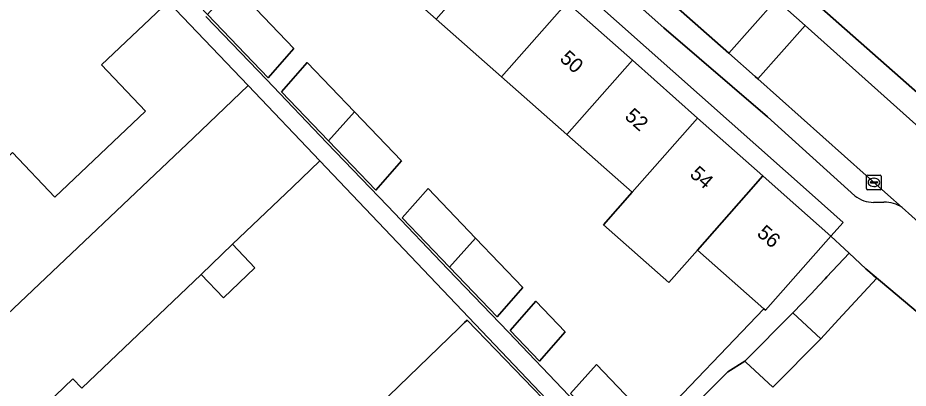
# Model space of a CAD drawing. Extents: x 162523 to 163266, y 381230 to 382050.
# Drawn here: x 162936.1 to 162997.1, y 381486.8 to 381512.1 of the extents above; entities that cross this region are included whole.
import ezdxf

# ---------------------------------------------------------------- set-up
doc = ezdxf.new("R2010")
doc.units = 0
for name, color, linetype in [('IMGEO_Erf', 7, 'Continuous'), ('IMGEO_Kolk', 7, 'Continuous'), ('IMGEO_Muur', 7, 'Continuous'), ('IMGEO_Pand', 7, 'Continuous'), ('IMGEO_Pand_nummerreeks', 7, 'Continuous'), ('IMGEO_Parkeervlak_open', 7, 'Continuous'), ('IMGEO_Rijbaan_lokaal_open', 7, 'Continuous'), ('IMGEO_Voetpad_open', 7, 'Continuous')]:
    doc.layers.add(name, color=color, linetype=linetype)

msp = doc.modelspace()

# ---------------------------------------------------------------- linework, layer by layer
at = {"layer": 'IMGEO_Erf'}
for points in [[(162979.592, 381528.722), (162975.111, 381532.694), (162970.631, 381536.665), (162966.151, 381540.636), (162961.584, 381544.684), (162956.963, 381548.78), (162952.356, 381552.864), (162947.718, 381556.975), (162944.876, 381553.79), (162964.471, 381536.308), (162999.264, 381505.633), (162999.351, 381505.556), (163000, 381506.279), (163002.177, 381508.703), (163000, 381510.633), (162997.512, 381512.838), (162993.032, 381516.809), (162988.552, 381520.78), (162984.072, 381524.751)], [(162952.337, 381533.894), (162951.47, 381532.913), (162955.868, 381529.014), (162960.335, 381525.054), (162964.802, 381521.094), (162969.269, 381517.134), (162973.736, 381513.174), (162978.203, 381509.214), (162982.67, 381505.254), (162987.138, 381501.293), (162988.597, 381500), (162991.799, 381497.161), (162992.639, 381498.114), (162990.515, 381500)], [(162953.249, 381508.02), (162949.104, 381512.345), (162945.876, 381515.714), (162947.643, 381517.713), (162950.871, 381514.344), (162955.016, 381510.02)], [(162959.161, 381505.694), (162962.39, 381502.325), (162960.624, 381500.325), (162957.395, 381503.695), (162954.167, 381507.063), (162955.933, 381509.063)], [(162967.45, 381497.045), (162970.697, 381493.657), (162968.931, 381491.657), (162965.683, 381495.045), (162962.438, 381498.432), (162964.205, 381500.432)], [(162971.597, 381492.718), (162973.605, 381490.623), (162971.838, 381488.624), (162969.831, 381490.718)], [(162966.696, 381491.253), (162966.876, 381491.427), (162976.591, 381481.38), (162976.41, 381481.206), (162969.171, 381474.207), (162968.934, 381474.452), (162959.589, 381484.117), (162959.457, 381484.253), (162966.311, 381490.881)]]:
    msp.add_lwpolyline(points, close=True, dxfattribs=at)
for points in [[(162948.991, 381512.217), (162953.136, 381507.892), (162957.281, 381503.566), (162961.425, 381499.243), (162965.57, 381494.917), (162969.718, 381490.59), (162973.859, 381486.269), (162977.616, 381482.348), (162977.739, 381482.466), (162973.972, 381486.397), (162975.739, 381488.396), (162979.659, 381484.306), (162987.204, 381492.203), (162982.656, 381496.222), (162980.699, 381494.008), (162976.227, 381497.959), (162978.183, 381500.174), (162973.709, 381504.128), (162969.235, 381508.081), (162964.762, 381512.033), (162960.288, 381515.986)], [(162935.735, 381502.902), (162938.652, 381499.847), (162944.855, 381505.737), (162941.842, 381508.894), (162946.401, 381513.222)], [(162903.859, 381500), (162947.952, 381453.669), (162957.442, 381462.564), (162967.253, 381472.252), (162976.751, 381481.351), (162956.799, 381502.326), (162954.918, 381500.53), (162950.818, 381496.616), (162952.35, 381495.012), (162950.188, 381492.947), (162948.656, 381494.551), (162940.499, 381486.762), (162939.885, 381487.405), (162933.973, 381481.762)], [(163001.938, 381488.428), (162994.2, 381494.937), (162994.918, 381494.271), (162992.317, 381491.468), (162991.116, 381490.145), (162987.816, 381486.838), (162985.97, 381488.548), (162985.898, 381488.614), (162984.752, 381487.882), (162980.521, 381483.642)]]:
    msp.add_lwpolyline(points, dxfattribs=at)
at = {"layer": 'IMGEO_Kolk'}
for p, q in [((162994.249, 381500.427), (162994.249, 381501.279)), ((162994.324, 381501.353), (162995.176, 381501.353)), ((162995.25, 381501.279), (162995.25, 381500.427)), ((162994.508, 381500.847), (162994.508, 381500.859)), ((162994.946, 381500.81), (162994.548, 381500.81)), ((162994.551, 381500.896), (162994.949, 381500.896)), ((162994.76, 381500.573), (162994.735, 381500.573)), ((162994.737, 381501.133), (162994.762, 381501.133)), ((162994.992, 381500.859), (162994.992, 381500.847)), ((162995.176, 381500.353), (162994.324, 381500.353))]:
    msp.add_line(p, q, dxfattribs=at)
for points in [[(162994.249, 381500.427), (162994.249, 381501.279)], [(162994.324, 381501.353), (162995.176, 381501.353)], [(162995.25, 381501.279), (162995.25, 381500.427)], [(162995.176, 381500.353), (162994.324, 381500.353)]]:
    msp.add_lwpolyline(points, dxfattribs=at)
for centre, radius, start, end in [((162994.326, 381501.277), 0.0765, 91.55205, 178.44795), ((162994.326, 381501.277), 0.0765, 91.55205, 178.44795), ((162995.174, 381501.277), 0.0765, 1.55205, 88.44795), ((162995.174, 381501.277), 0.0765, 1.55205, 88.44795), ((162994.548, 381500.856), 0.0403, 85.87752, 175.75265), ((162994.545, 381500.846), 0.0366, 178.93798, 274.71019), ((162994.949, 381500.853), 0.043, 264.86636, 352.45326), ((162994.953, 381500.858), 0.0386, 1.73085, 96.63898), ((162994.326, 381500.429), 0.0765, 181.55205, 268.44795), ((162994.326, 381500.429), 0.0765, 181.55205, 268.44795), ((162995.174, 381500.429), 0.0765, 271.55205, 358.44795), ((162995.174, 381500.429), 0.0765, 271.55205, 358.44795)]:
    msp.add_arc(centre, radius, start, end, dxfattribs=at)
for centre, major_axis, ratio, start_param, end_param in [((162994.736, 381500.853), (-0.387, 0.002), 0.722429, 4.712389, 7.853982), ((162994.761, 381500.853), (-0.39, 0.002), 0.717154, 1.570796, 4.712389)]:
    msp.add_ellipse(centre, major_axis=major_axis, ratio=ratio, start_param=start_param, end_param=end_param, dxfattribs=at)
at = {"layer": 'IMGEO_Muur'}
msp.add_lwpolyline([(162994.2, 381494.937), (163001.938, 381488.428)], dxfattribs=at)
at = {"layer": 'IMGEO_Pand'}
for points in [[(162960.288, 381515.986), (162964.762, 381512.033), (162969.269, 381517.134), (162964.802, 381521.094), (162964.729, 381521.012)], [(162969.235, 381508.081), (162973.736, 381513.174), (162969.269, 381517.134), (162964.762, 381512.033)], [(162950.871, 381514.344), (162949.104, 381512.345), (162953.249, 381508.02), (162955.016, 381510.02)], [(162933.844, 381493.401), (162935.349, 381491.825), (162935.374, 381491.799), (162948.134, 381503.914), (162951.885, 381507.475), (162946.401, 381513.222), (162941.842, 381508.894), (162944.855, 381505.737), (162938.652, 381499.847), (162935.735, 381502.902), (162930.729, 381498.15), (162932.581, 381496.211), (162931.838, 381495.502), (162928.973, 381492.767), (162927.06, 381494.771), (162926.828, 381494.547), (162920.503, 381488.564), (162921.104, 381487.935), (162921.086, 381487.132), (162921.802, 381486.381), (162922.707, 381486.36), (162924.5, 381484.482), (162928.117, 381487.935)], [(162978.203, 381509.214), (162973.736, 381513.174), (162969.235, 381508.081), (162973.709, 381504.128)], [(162978.203, 381509.214), (162973.709, 381504.128), (162978.183, 381500.174), (162982.67, 381505.254)], [(162955.933, 381509.063), (162954.167, 381507.063), (162957.395, 381503.695), (162959.161, 381505.694)], [(162954.918, 381500.53), (162956.799, 381502.326), (162951.885, 381507.475), (162948.134, 381503.914), (162935.374, 381491.799), (162925.959, 381482.861), (162926.338, 381482.463), (162929.997, 381478.63), (162930.329, 381478.283), (162933.973, 381481.762), (162939.885, 381487.405), (162940.499, 381486.762), (162948.656, 381494.551), (162950.818, 381496.616)], [(162959.161, 381505.694), (162957.395, 381503.695), (162960.624, 381500.325), (162962.39, 381502.325)], [(162987.138, 381501.293), (162982.67, 381505.254), (162978.183, 381500.174), (162976.227, 381497.959), (162980.699, 381494.008), (162982.656, 381496.222), (162985.995, 381500)], [(162988.597, 381500), (162987.138, 381501.293), (162985.995, 381500), (162982.656, 381496.222), (162987.204, 381492.203), (162987.324, 381492.097), (162991.799, 381497.161)], [(162964.205, 381500.432), (162962.438, 381498.432), (162965.683, 381495.045), (162967.45, 381497.045)], [(162967.45, 381497.045), (162965.683, 381495.045), (162968.931, 381491.657), (162970.697, 381493.657)], [(162950.818, 381496.616), (162948.656, 381494.551), (162950.188, 381492.947), (162952.35, 381495.012)], [(162994.2, 381494.937), (162993.042, 381496.011), (162991.529, 381494.38), (162991.399, 381494.24), (162990.998, 381493.808), (162990.46, 381493.228), (162989.198, 381491.921), (162991.116, 381490.145), (162992.317, 381491.468), (162994.918, 381494.271)], [(162971.597, 381492.718), (162969.831, 381490.718), (162971.838, 381488.624), (162973.605, 381490.623)], [(162966.311, 381490.881), (162959.457, 381484.253), (162959.589, 381484.117), (162968.934, 381474.452), (162969.171, 381474.207), (162976.41, 381481.206), (162976.591, 381481.38), (162966.876, 381491.427), (162966.696, 381491.253)], [(162991.116, 381490.145), (162989.198, 381491.921), (162985.898, 381488.614), (162985.97, 381488.548), (162987.816, 381486.838)], [(162975.739, 381488.396), (162973.972, 381486.397), (162977.739, 381482.466), (162979.659, 381484.306)]]:
    msp.add_lwpolyline(points, close=True, dxfattribs=at)
at = {"layer": 'IMGEO_Parkeervlak_open'}
for points in [[(162956.193, 381532.9), (162980.348, 381511.432), (162987.45, 381505.344), (162993.451, 381499.941)], [(162996.681, 381499.132), (162995.709, 381500), (162986.801, 381507.947), (162986.615, 381508.113), (162984.813, 381509.7), (162969.457, 381523.224)], [(162994.725, 381499.487), (162995.436, 381499.5)]]:
    msp.add_lwpolyline(points, dxfattribs=at)
for centre, radius, start, end in [((162994.699, 381501.43), 1.943, 230.02015, 270.752), ((162995.474, 381497.338), 2.163, 56.06661, 90.99989)]:
    msp.add_arc(centre, radius, start, end, dxfattribs=at)
at = {"layer": 'IMGEO_Rijbaan_lokaal_open'}
for points in [[(162984.813, 381509.7), (162988.055, 381513.37), (162985.328, 381515.807), (162967.702, 381531.321), (162951.542, 381545.572), (162948.19, 381541.79), (162948.645, 381541.401), (162953.154, 381537.552), (162954.811, 381536.096), (162969.457, 381523.224)], [(162986.801, 381507.947), (162990.032, 381511.604), (162988.055, 381513.37), (162984.813, 381509.7), (162986.615, 381508.113)]]:
    msp.add_lwpolyline(points, close=True, dxfattribs=at)
msp.add_lwpolyline([(163003.39, 381499.675), (163003.021, 381500), (163000.93, 381501.868), (163000, 381502.699), (162990.032, 381511.604), (162986.801, 381507.947), (162995.709, 381500), (162996.681, 381499.132), (162997.351, 381498.535), (162999.813, 381496.339), (163000, 381496.173), (163001.157, 381495.148), (163011.645, 381485.853), (163012.448, 381485.053)], dxfattribs=at)
at = {"layer": 'IMGEO_Voetpad_open'}
for points in [[(162943.227, 381555.261), (162945.207, 381557.469), (162934.089, 381566.322), (162927.51, 381571.799), (162924.941, 381574.118), (162920.788, 381577.63), (162917.851, 381574.024), (162924.31, 381568.58), (162925.474, 381567.598), (162933.285, 381561.036), (162949.507, 381547.316), (162950.943, 381546.101), (162951.542, 381545.572), (162967.702, 381531.321), (162985.328, 381515.807), (162988.055, 381513.37), (162990.032, 381511.604), (163000, 381502.699), (163000.93, 381501.868), (163003.021, 381500), (163003.39, 381499.675), (163015.045, 381489.291)], [(162917.604, 381567.698), (162914.638, 381570.187), (162911.586, 381566.758), (162915.836, 381563.236), (162917.487, 381561.716), (162933.857, 381548.227), (162936.56, 381545.986), (162938.022, 381544.713), (162938.851, 381545.67), (162949.96, 381535.97), (162952.337, 381533.894), (162990.515, 381500), (162992.639, 381498.114), (162991.799, 381497.161), (162992.727, 381496.303), (162993.042, 381496.011), (162994.2, 381494.937), (163001.938, 381488.428), (163007.418, 381483.364), (163011.108, 381480.036), (163013.791, 381482.55), (163013.743, 381482.895)], [(163018.083, 381487.606), (163018.169, 381487.591), (163018.256, 381487.577), (163021.443, 381491.253), (163017.754, 381494.597), (163012.197, 381499.727), (163011.079, 381500.727), (163006.828, 381504.532), (163006.125, 381505.164), (163005.155, 381506.019), (163003.24, 381507.708), (163002.177, 381508.703), (163000, 381506.279), (162999.351, 381505.556), (162999.264, 381505.633), (162964.471, 381536.308), (162944.876, 381553.79), (162943.227, 381555.261)], [(162993.451, 381499.941), (162987.45, 381505.344), (162980.348, 381511.432), (162956.193, 381532.9)], [(162946.401, 381513.222), (162951.885, 381507.475), (162956.799, 381502.326), (162976.751, 381481.351)], [(162973.859, 381486.269), (162969.718, 381490.59), (162965.57, 381494.917), (162961.425, 381499.243), (162957.281, 381503.566), (162953.136, 381507.892), (162948.991, 381512.217)], [(162995.436, 381499.5), (162994.725, 381499.487)], [(163001.289, 381493.61), (163001.293, 381494.333), (163001.157, 381495.148), (163000, 381496.173), (162999.813, 381496.339), (162997.351, 381498.535), (162996.681, 381499.132)], [(162980.521, 381483.642), (162984.752, 381487.882), (162985.898, 381488.614), (162989.198, 381491.921), (162990.46, 381493.228), (162990.998, 381493.808), (162991.399, 381494.24), (162991.529, 381494.38), (162993.042, 381496.011), (162992.727, 381496.303), (162991.799, 381497.161), (162987.324, 381492.097), (162987.204, 381492.203), (162979.659, 381484.306)]]:
    msp.add_lwpolyline(points, dxfattribs=at)
for centre, radius, start, end in [((162994.699, 381501.43), 1.943, 230.02015, 270.752), ((162995.474, 381497.338), 2.163, 56.06661, 90.99989)]:
    msp.add_arc(centre, radius, start, end, dxfattribs=at)

# ---------------------------------------------------------------- texts
at = {"layer": 'IMGEO_Pand_nummerreeks'}
for s, rotation, p in [('50', 318.36866, (162973.169, 381509.238)), ('52', 318.36866, (162977.618, 381505.284)), ('54', 318.36889, (162982.074, 381501.324)), ('56', 319.0106, (162986.673, 381497.27))]:
    msp.add_text(s, height=1, rotation=rotation, dxfattribs=at).set_placement(p)

doc.saveas('drawing.dxf')
